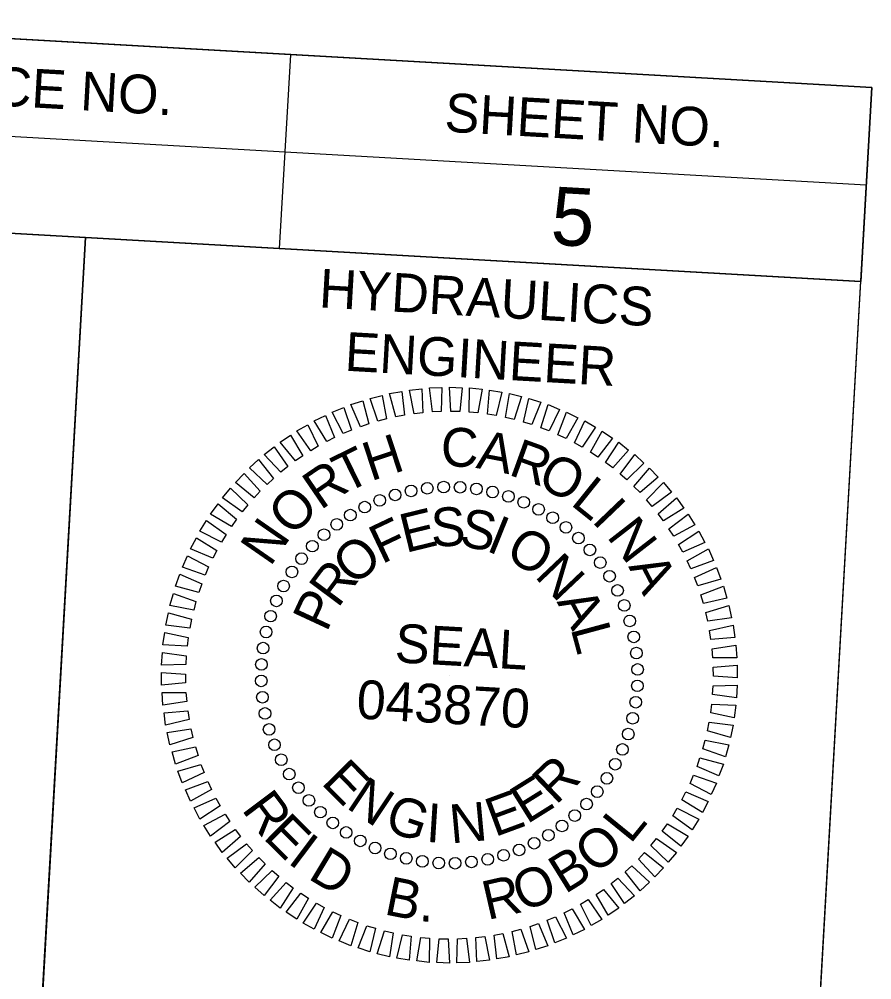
# Model space of a CAD drawing. Extents: x 2604316 to 2606605, y 617090 to 619543.
# Drawn here: x 2605939.3 to 2606049.1, y 618872.2 to 618996 of the extents above; entities that cross this region are included whole.
import ezdxf

# ---------------------------------------------------------------- set-up
doc = ezdxf.new("R2010")
doc.units = 0
for name, color, linetype in [('Default', 7, 'Continuous'), ('Sheet Data Field CELL', 7, 'Continuous'), ('Sheet PE Seal Cell', 7, 'Continuous'), ('Sheet Plan And Profile CELL', 7, 'Continuous')]:
    doc.layers.add(name, color=color, linetype=linetype)

msp = doc.modelspace()

# ---------------------------------------------------------------- linework, layer by layer
at = {"layer": 'Default'}
msp.add_line((2605947.83, 618967.86), (2605941.44, 618855.58), dxfattribs=at)
at = {"layer": 'Sheet PE Seal Cell'}
msp.add_line((2605994.69, 618911.46), (2605994.69, 618911.46), dxfattribs=at)
for points in [[(2605987.79, 618944.74), (2605986.98, 618947.76), (2605988.57, 618948.03), (2605988.92, 618944.96)], [(2605990.13, 618945.14), (2605989.53, 618948.2), (2605991.14, 618948.37), (2605991.27, 618945.28)], [(2605992.49, 618945.38), (2605992.11, 618948.47), (2605993.72, 618948.52), (2605993.63, 618945.44)], [(2605994.86, 618945.45), (2605994.7, 618948.56), (2605996.31, 618948.5), (2605996.01, 618945.43)], [(2605997.24, 618945.35), (2605997.29, 618948.47), (2605998.89, 618948.3), (2605998.37, 618945.26)], [(2605999.59, 618945.09), (2605999.86, 618948.2), (2606001.45, 618947.91), (2606000.72, 618944.92)], [(2606001.93, 618944.67), (2606002.41, 618947.75), (2606003.98, 618947.35), (2606003.04, 618944.41)], [(2605983.23, 618943.46), (2605982, 618946.33), (2605983.54, 618946.82), (2605984.31, 618943.83)], [(2605985.49, 618944.18), (2605984.47, 618947.13), (2605986.04, 618947.51), (2605986.59, 618944.48)], [(2606004.23, 618944.08), (2606004.92, 618947.12), (2606006.46, 618946.62), (2606005.32, 618943.75)], [(2605981.02, 618942.58), (2605979.6, 618945.36), (2605981.1, 618945.96), (2605982.08, 618943.03)], [(2606006.48, 618943.34), (2606007.39, 618946.32), (2606008.88, 618945.71), (2606007.55, 618942.93)], [(2606008.67, 618942.44), (2606009.79, 618945.35), (2606011.24, 618944.64), (2606009.71, 618941.96)], [(2605978.89, 618941.55), (2605977.28, 618944.23), (2605978.73, 618944.93), (2605979.9, 618942.07)], [(2606010.8, 618941.39), (2606012.12, 618944.22), (2606013.51, 618943.4), (2606011.8, 618940.83)], [(2605976.83, 618940.38), (2605975.03, 618942.93), (2605976.44, 618943.73), (2605977.8, 618940.97)], [(2606012.85, 618940.19), (2606014.36, 618942.92), (2606015.69, 618942.01), (2606013.81, 618939.57)], [(2605974.85, 618939.06), (2605972.88, 618941.48), (2605974.23, 618942.38), (2605975.79, 618939.72)], [(2606014.81, 618938.85), (2606016.51, 618941.47), (2606017.77, 618940.47), (2606015.72, 618938.17)], [(2605972.97, 618937.61), (2605970.84, 618939.89), (2605972.12, 618940.88), (2605973.86, 618938.33)], [(2605971.2, 618936.03), (2605968.92, 618938.16), (2605970.12, 618939.23), (2605972.04, 618936.81)], [(2606016.67, 618937.38), (2606018.55, 618939.88), (2606019.74, 618938.79), (2606017.54, 618936.63)], [(2606018.43, 618935.79), (2606020.47, 618938.14), (2606021.59, 618936.98), (2606019.24, 618934.98)], [(2605969.55, 618934.33), (2605967.12, 618936.29), (2605968.25, 618937.45), (2605970.32, 618935.17)], [(2605968.01, 618932.52), (2605965.45, 618934.31), (2605966.5, 618935.54), (2605968.73, 618933.41)], [(2606020.07, 618934.07), (2606022.27, 618936.28), (2606023.3, 618935.04), (2606020.82, 618933.21)], [(2606021.58, 618932.24), (2606023.93, 618934.3), (2606024.88, 618932.98), (2606022.27, 618931.33)], [(2605966.61, 618930.61), (2605963.93, 618932.21), (2605964.89, 618933.52), (2605967.26, 618931.55)], [(2606022.97, 618930.32), (2606025.46, 618932.2), (2606026.3, 618930.83), (2606023.59, 618929.36)], [(2605965.34, 618928.61), (2605962.56, 618930.02), (2605963.42, 618931.39), (2605965.93, 618929.59)], [(2605964.22, 618926.52), (2605961.34, 618927.73), (2605962.11, 618929.16), (2605964.73, 618927.54)], [(2606024.21, 618928.3), (2606026.83, 618930), (2606027.58, 618928.57), (2606024.77, 618927.3)], [(2605963.24, 618924.36), (2605960.29, 618925.37), (2605960.95, 618926.84), (2605963.68, 618925.41)], [(2606025.32, 618926.2), (2606028.04, 618927.72), (2606028.69, 618926.24), (2606025.8, 618925.16)], [(2606026.27, 618924.03), (2606029.1, 618925.35), (2606029.64, 618923.83), (2606026.68, 618922.96)], [(2605962.42, 618922.13), (2605959.4, 618922.93), (2605959.96, 618924.45), (2605962.79, 618923.21)], [(2606027.07, 618921.79), (2606029.98, 618922.92), (2606030.42, 618921.36), (2606027.41, 618920.7)], [(2605961.75, 618919.85), (2605958.69, 618920.44), (2605959.14, 618921.99), (2605962.04, 618920.96)], [(2606027.71, 618919.51), (2606030.69, 618920.43), (2606031.02, 618918.84), (2606027.97, 618918.4)], [(2605961.24, 618917.53), (2605958.15, 618917.91), (2605958.49, 618919.49), (2605961.46, 618918.66)], [(2605960.9, 618915.19), (2605957.79, 618915.35), (2605958.02, 618916.94), (2605961.04, 618916.32)], [(2606028.19, 618917.19), (2606031.23, 618917.89), (2606031.45, 618916.29), (2606028.37, 618916.06)], [(2605960.72, 618912.82), (2605957.6, 618912.76), (2605957.72, 618914.37), (2605960.78, 618913.96)], [(2606028.51, 618914.83), (2606031.59, 618915.33), (2606031.7, 618913.71), (2606028.61, 618913.7)], [(2605960.71, 618910.45), (2605957.6, 618910.17), (2605957.61, 618911.79), (2605960.69, 618911.59)], [(2606028.66, 618912.47), (2606031.77, 618912.74), (2606031.76, 618911.13), (2606028.69, 618911.32)], [(2606028.65, 618910.09), (2606031.77, 618910.15), (2606031.65, 618908.54), (2606028.59, 618908.95)], [(2605960.87, 618908.08), (2605957.78, 618907.59), (2605957.68, 618909.2), (2605960.76, 618909.22)], [(2605961.18, 618905.73), (2605958.14, 618905.02), (2605957.93, 618906.62), (2605961, 618906.86)], [(2606028.47, 618907.73), (2606031.59, 618907.57), (2606031.36, 618905.97), (2606028.34, 618906.59)], [(2605961.66, 618903.41), (2605958.68, 618902.49), (2605958.35, 618904.07), (2605961.4, 618904.52)], [(2606028.13, 618905.38), (2606031.23, 618905.01), (2606030.88, 618903.43), (2606027.91, 618904.26)], [(2606027.63, 618903.06), (2606030.69, 618902.47), (2606030.24, 618900.92), (2606027.33, 618901.96)], [(2605962.31, 618901.12), (2605959.39, 618900), (2605958.96, 618901.56), (2605961.97, 618902.21)], [(2606026.96, 618900.79), (2606029.98, 618899.98), (2606029.41, 618898.47), (2606026.59, 618899.7)], [(2605963.11, 618898.89), (2605960.28, 618897.57), (2605959.73, 618899.09), (2605962.69, 618899.95)], [(2606026.14, 618898.56), (2606029.09, 618897.55), (2606028.42, 618896.08), (2606025.69, 618897.51)], [(2605964.06, 618896.72), (2605961.33, 618895.2), (2605960.68, 618896.68), (2605963.57, 618897.75)], [(2606025.16, 618896.4), (2606028.03, 618895.18), (2606027.27, 618893.76), (2606024.64, 618895.38)], [(2605965.16, 618894.62), (2605962.55, 618892.91), (2605961.8, 618894.34), (2605964.61, 618895.61)], [(2605966.41, 618892.6), (2605963.92, 618890.72), (2605963.07, 618892.09), (2605965.79, 618893.55)], [(2606024.04, 618894.31), (2606026.82, 618892.9), (2606025.96, 618891.53), (2606023.45, 618893.33)], [(2606022.77, 618892.3), (2606025.45, 618890.7), (2606024.49, 618889.4), (2606022.11, 618891.37)], [(2605967.79, 618890.67), (2605965.44, 618888.62), (2605964.5, 618889.93), (2605967.1, 618891.58)], [(2605969.31, 618888.85), (2605967.11, 618886.64), (2605966.07, 618887.88), (2605968.56, 618889.71)], [(2606021.36, 618890.39), (2606023.92, 618888.61), (2606022.88, 618887.37), (2606020.65, 618889.5)], [(2606019.83, 618888.58), (2606022.26, 618886.62), (2606021.13, 618885.46), (2606019.05, 618887.75)], [(2605970.95, 618887.13), (2605968.9, 618884.77), (2605967.79, 618885.94), (2605970.14, 618887.94)], [(2605972.7, 618885.53), (2605970.83, 618883.04), (2605969.63, 618884.13), (2605971.84, 618886.28)], [(2606018.17, 618886.88), (2606020.46, 618884.76), (2606019.25, 618883.68), (2606017.34, 618886.1)], [(2605974.57, 618884.06), (2605972.87, 618881.44), (2605971.6, 618882.44), (2605973.65, 618884.75)], [(2606016.4, 618885.31), (2606018.53, 618883.03), (2606017.25, 618882.04), (2606015.51, 618884.59)], [(2605976.53, 618882.73), (2605975.02, 618879.99), (2605973.68, 618880.9), (2605975.57, 618883.35)], [(2606014.52, 618883.85), (2606016.49, 618881.43), (2606015.15, 618880.54), (2606013.59, 618883.2)], [(2605978.57, 618881.53), (2605977.26, 618878.7), (2605975.86, 618879.51), (2605977.57, 618882.08)], [(2606012.55, 618882.54), (2606014.34, 618879.98), (2606012.94, 618879.18), (2606011.57, 618881.95)], [(2605980.7, 618880.48), (2605979.59, 618877.56), (2605978.14, 618878.28), (2605979.66, 618880.96)], [(2606010.49, 618881.36), (2606012.1, 618878.69), (2606010.64, 618877.99), (2606009.47, 618880.84)], [(2605982.9, 618879.58), (2605981.99, 618876.59), (2605980.49, 618877.21), (2605981.83, 618879.99)], [(2606008.35, 618880.33), (2606009.77, 618877.56), (2606008.27, 618876.96), (2606007.3, 618879.89)], [(2605985.15, 618878.83), (2605984.45, 618875.79), (2605982.92, 618876.3), (2605984.06, 618879.16)], [(2605987.45, 618878.25), (2605986.96, 618875.16), (2605985.4, 618875.56), (2605986.33, 618878.5)], [(2606003.89, 618878.74), (2606004.91, 618875.79), (2606003.34, 618875.4), (2606002.78, 618878.44)], [(2606006.15, 618879.46), (2606007.37, 618876.59), (2606005.83, 618876.09), (2606005.07, 618879.08)], [(2605989.78, 618877.82), (2605989.51, 618874.71), (2605987.92, 618875), (2605988.65, 618878)], [(2605992.14, 618877.56), (2605992.09, 618874.44), (2605990.48, 618874.62), (2605991, 618877.66)], [(2605994.51, 618877.47), (2605994.68, 618874.35), (2605993.06, 618874.42), (2605993.37, 618877.49)], [(2605996.88, 618877.54), (2605997.27, 618874.44), (2605995.65, 618874.39), (2605995.74, 618877.48)], [(2605999.24, 618877.77), (2605999.84, 618874.71), (2605998.23, 618874.55), (2605998.11, 618877.63)], [(2606001.58, 618878.17), (2606002.39, 618875.16), (2606000.8, 618874.89), (2606000.46, 618877.95)]]:
    msp.add_lwpolyline(points, close=True, dxfattribs=at)
for centre in [(2605987.7, 618934.68), (2605989.75, 618935.2), (2605991.84, 618935.54), (2605993.95, 618935.7), (2605996.07, 618935.67), (2605998.17, 618935.46), (2606000.25, 618935.06), (2606002.29, 618934.49), (2605985.71, 618933.98), (2606004.26, 618933.74), (2605981.93, 618932.08), (2605983.78, 618933.11), (2606006.17, 618932.82), (2605980.18, 618930.89), (2606007.99, 618931.74), (2605978.54, 618929.55), (2606009.7, 618930.5), (2606011.31, 618929.12), (2605977.03, 618928.08), (2606012.78, 618927.6), (2605975.65, 618926.47), (2606014.12, 618925.96), (2605974.41, 618924.76), (2606015.31, 618924.21), (2605973.33, 618922.94), (2606016.34, 618922.37), (2605972.41, 618921.03), (2606017.21, 618920.44), (2605971.66, 618919.06), (2606017.91, 618918.44), (2605971.08, 618917.02), (2606018.43, 618916.39), (2605970.69, 618914.94), (2606018.77, 618914.3), (2605970.48, 618912.84), (2606018.93, 618912.19), (2605970.45, 618910.72), (2606018.9, 618910.08), (2605970.61, 618908.61), (2606018.69, 618907.97), (2605970.94, 618906.52), (2606018.29, 618905.9), (2605971.47, 618904.47), (2606017.72, 618903.86), (2605972.16, 618902.48), (2606016.97, 618901.88), (2605973.03, 618900.55), (2606016.05, 618899.98), (2605974.06, 618898.7), (2606014.97, 618898.16), (2605975.25, 618896.95), (2606013.73, 618896.44), (2605976.59, 618895.31), (2605978.07, 618893.8), (2606012.35, 618894.84), (2605979.67, 618892.42), (2606010.83, 618893.36), (2605981.39, 618891.18), (2606009.19, 618892.02), (2605983.21, 618890.1), (2606007.44, 618890.83), (2605985.11, 618889.18), (2606003.67, 618888.93), (2606005.6, 618889.8), (2605987.09, 618888.43), (2605989.13, 618887.85), (2605991.2, 618887.46), (2605999.62, 618887.72), (2606001.67, 618888.24), (2605993.31, 618887.25), (2605995.42, 618887.22), (2605997.53, 618887.38)]:
    msp.add_circle(centre, 0.75, dxfattribs=at)
at = {"layer": 'Sheet Plan And Profile CELL'}
for p, q in [((2605974.21, 618991.4), (2605972.78, 618966.44)), ((2605848.65, 618986.03), (2606048.37, 618974.65))]:
    msp.add_line(p, q, dxfattribs=at)
for points in [[(2606049.09, 618987.18), (2604551.51, 619072.48), (2604491.81, 618024.18), (2605989.38, 617938.88)], [(2605849.36, 618998.56), (2606049.09, 618987.18), (2606047.66, 618962.17), (2605847.94, 618973.55)], [(2605847.94, 618973.55), (2605947.83, 618967.86), (2605941.43, 618855.53), (2605841.55, 618861.24)], [(2605947.83, 618967.86), (2606047.65, 618962.19), (2606041.27, 618849.85), (2605941.43, 618855.53)]]:
    msp.add_lwpolyline(points, close=True, dxfattribs=at)

# ---------------------------------------------------------------- texts
at = {"layer": 'Default'}
for s, p in [('HYDRAULICS', (2605977.82, 618958.86)), ('ENGINEER', (2605981.13, 618950.7))]:
    msp.add_text(s, height=5, rotation=356.7403, dxfattribs=at).set_placement(p)
at = {"layer": 'Sheet Data Field CELL'}
msp.add_text('5', height=7.5, rotation=356.7403, dxfattribs=at).set_placement((2606007.62, 618966.96))
at = {"layer": 'Sheet PE Seal Cell'}
for s, rotation, p in [('C', 358.7021, (2605993.55, 618938.37)), ('A', 349.197, (2605998.01, 618938.18)), ('H', 18.3413, (2605984.57, 618936.42)), ('R', 340.1496, (2606002.17, 618937.33)), ('T', 26.1305, (2605981.28, 618934.82)), ('O', 331.9409, (2606005.78, 618936)), ('R', 34.3392, (2605978.08, 618932.66)), ('L', 321.2157, (2606010.16, 618933.5)), ('O', 45.0643, (2605974.43, 618929.2)), ('I', 313.7506, (2606012.89, 618931.31)), ('E', 13.7262, (2605989.04, 618927.19)), ('S', 1.964, (2605992.37, 618928.01)), ('S', 350.005, (2605995.85, 618928.13)), ('N', 55.2748, (2605971.6, 618925.33)), ('F', 25.4042, (2605985.97, 618925.72)), ('I', 338.0461, (2605999.28, 618927.53)), ('N', 307.8106, (2606014.85, 618929.32)), ('O', 329.2906, (2606001.67, 618926.65)), ('O', 41.2129, (2605982.42, 618922.81)), ('N', 313.4818, (2606005.55, 618924.17)), ('R', 53.3124, (2605980.31, 618919.99)), ('A', 297.6002, (2606017.69, 618925.46)), ('P', 65.0746, (2605978.87, 618916.88)), ('A', 298.4318, (2606008.47, 618920.91)), ('SEAL', 356.7403, (2605987.57, 618913.12)), ('L', 285.0959, (2606010.28, 618917.48)), ('043870', 356.7403, (2605982.64, 618905.88)), ('E', 314.5909, (2605978.06, 618897.52)), ('R', 43.7832, (2606008.39, 618894.63)), ('N', 326.3531, (2605981.25, 618894.43)), ('E', 32.021, (2606004.67, 618892.19)), ('R', 306.9028, (2605967.83, 618894.14)), ('G', 341.4032, (2605986.13, 618891.52)), ('E', 20.2587, (2606000.53, 618890.56)), ('I', 356.4532, (2605991.6, 618889.98)), ('N', 5.2087, (2605994.91, 618889.76)), ('E', 315.1115, (2605970.57, 618890.49)), ('L', 50.9163, (2606017.99, 618889.59)), ('I', 323.0913, (2605973.72, 618887.34)), ('O', 40.1911, (2606013.51, 618885.64)), ('B', 31.849, (2606009.57, 618883.18)), ('D', 329.0313, (2605976.33, 618885.3)), ('O', 21.1238, (2606004.04, 618880.9)), ('B', 348.6038, (2605986.15, 618880.66)), ('R', 12.9152, (2605999.59, 618879.88)), ('.', 356.9459, (2605990.71, 618879.75))]:
    msp.add_text(s, height=5, rotation=rotation, dxfattribs=at).set_placement(p)
at = {"layer": 'Sheet Plan And Profile CELL'}
for s, height, p in [('PROJECT REFERENCE NO.', 5.0001, (2605871.03, 618988.61)), ('SHEET NO.', 5, (2605993.98, 618981.51))]:
    msp.add_text(s, height=height, rotation=356.7403, dxfattribs=at).set_placement(p)

doc.saveas('drawing.dxf')
